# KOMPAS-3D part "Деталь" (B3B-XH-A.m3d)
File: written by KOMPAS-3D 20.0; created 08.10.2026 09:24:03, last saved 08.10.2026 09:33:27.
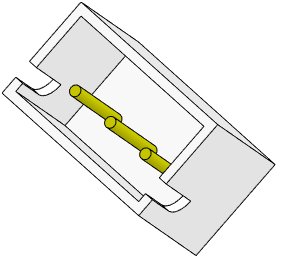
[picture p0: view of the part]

Document properties: Полное имя файла: D:\RicWork\Project-EPS32\box_compas\разъемы\B3B-XH-A.m3d

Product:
- Part/product: Деталь
    Масса: 0.00117184

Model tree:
1. Эскиз:1
2. Элемент выдавливания:1
     Расстояние 1 = 7
3. Эскиз:2  (with: Элемент выдавливания:1)
4. Элемент выдавливания:2
     Расстояние 2 = 6
5. Эскиз:3  (with: Элемент выдавливания:1)
6. Элемент выдавливания:3
     Расстояние 2 = 9.9
7. Скругление:1  (with: Элемент выдавливания:3)
     Радиус = 1
8. Эскиз:4  (with: Элемент выдавливания:1)
9. Элемент выдавливания:4
     Расстояние 1 = 3.4
10. Массив по сетке:1  (with: Элемент выдавливания:4, Эскиз:4)  (3 pattern instances)
     Шаг 1 = 10; Угол раствора = -90; Шаг 2 = 2.54
11. Эскиз:5  (with: Элемент выдавливания:2, Элемент выдавливания:4)
12. Элемент выдавливания:5
     Расстояние 1 = 5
